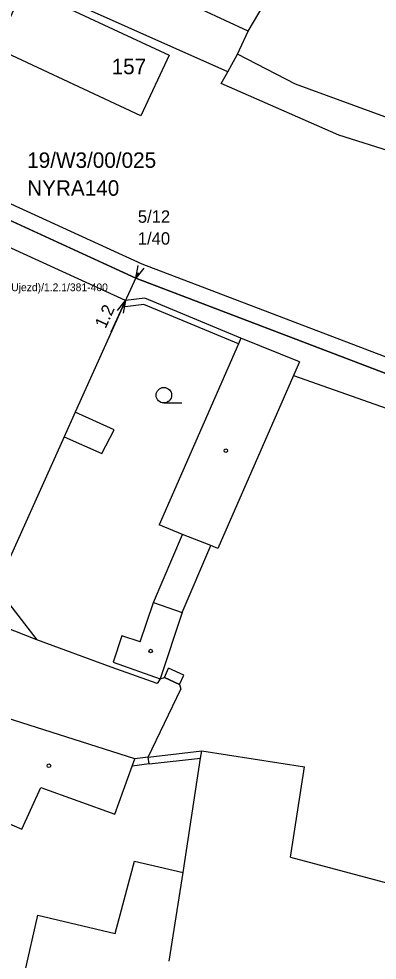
# Model space of a CAD drawing. Extents: x -836739 to -834468, y -1071001 to -1070126.
# Drawn here: x -836621.68 to -836604.33, y -1070455.07 to -1070409.44 of the extents above; entities that cross this region are included whole.
import ezdxf

# ---------------------------------------------------------------- set-up
doc = ezdxf.new("R2010")
doc.units = 0
for name, color, linetype in [('f001_pol_linie', 7, 'Continuous'), ('f001_pol_texty', 7, 'Continuous'), ('f001_pol_znacky', 7, 'Continuous'), ('f002_inz_linie_mimo_CETIN', 7, 'Continuous'), ('f004_popis_kab_zil', 7, 'Continuous'), ('f004_rozvadec_ann', 7, 'Continuous'), ('f006_osa_trasy', 7, 'Continuous'), ('f006_stp_koty', 7, 'Continuous'), ('f307_kabel_metal', 7, 'Continuous'), ('f307_rozvadec_ann', 7, 'Continuous')]:
    doc.layers.add(name, color=color, linetype=linetype)

msp = doc.modelspace()

# ---------------------------------------------------------------- linework, layer by layer
at = {"layer": 'f001_pol_linie'}
for points in [[(-836610.58, -1070410.04), (-836620.6, -1070405.38), (-836618.49, -1070400.85), (-836616.92, -1070397.47), (-836614.77, -1070392.87), (-836613.72, -1070393.26), (-836604.39, -1070397.96)], [(-836608.28, -1070412.62), (-836611.1, -1070411.16), (-836610.58, -1070410.04), (-836607.95, -1070405.59), (-836604.39, -1070397.96)], [(-836621.42, -1070407.93), (-836614.41, -1070411.21), (-836615.78, -1070414.14), (-836622.8, -1070410.87), (-836621.81, -1070408.77), (-836621.42, -1070407.93)], [(-836611.56, -1070412.01), (-836621.36, -1070407.64), (-836621.42, -1070407.93)], [(-836574.93, -1070422.97), (-836582.62, -1070420.71), (-836583.02, -1070422.31), (-836592.27, -1070419.48), (-836606.18, -1070415.08), (-836611.88, -1070412.58), (-836611.56, -1070412.01), (-836611.1, -1070411.16)], [(-836601.79, -1070414.98), (-836608.28, -1070412.62)], [(-836616.52, -1070423.1), (-836626.24, -1070418.65), (-836626.63, -1070418.47)], [(-836610.93, -1070424.93), (-836615.59, -1070422.99), (-836616.52, -1070423.1)], [(-836616.52, -1070423.1), (-836616.66, -1070423.42), (-836618.95, -1070428.51), (-836619.49, -1070429.7), (-836622.78, -1070437.01)], [(-836611.05, -1070425.2), (-836615.63, -1070423.3), (-836616.66, -1070423.42)], [(-836610.93, -1070424.93), (-836611.05, -1070425.2), (-836614.89, -1070433.98)], [(-836608.09, -1070426.07), (-836610.93, -1070424.93)], [(-836608.09, -1070426.07), (-836608.38, -1070426.73), (-836612.05, -1070435.12)], [(-836608.38, -1070426.73), (-836589.24, -1070433.48)], [(-836619.49, -1070429.7), (-836617.66, -1070430.52), (-836617.06, -1070429.36), (-836618.95, -1070428.51)], [(-836620.81, -1070439.55), (-836631.03, -1070435.52), (-836635.98, -1070433.29), (-836638.41, -1070431.73), (-836639.64, -1070430.3), (-836639.98, -1070429.29)], [(-836612.05, -1070435.12), (-836612.39, -1070434.98), (-836613.76, -1070434.44), (-836614.89, -1070433.98)], [(-836615.17, -1070437.74), (-836613.76, -1070434.44)], [(-836613.78, -1070438.23), (-836612.39, -1070434.98)], [(-836622.78, -1070437.01), (-836620.81, -1070439.55)], [(-836615.81, -1070439.65), (-836615.17, -1070437.74)], [(-836615.17, -1070437.74), (-836613.78, -1070438.23)], [(-836613.78, -1070438.23), (-836614.84, -1070441.43)], [(-836616.7, -1070439.35), (-836617.12, -1070440.63)], [(-836615.81, -1070439.65), (-836616.7, -1070439.35)], [(-836614.84, -1070441.43), (-836614.99, -1070441.66), (-836617.21, -1070440.88), (-836620.81, -1070439.55)], [(-836617.12, -1070440.63), (-836614.84, -1070441.43)], [(-836614.84, -1070441.43), (-836614.63, -1070441.38), (-836613.9, -1070441.72)], [(-836613.9, -1070441.72), (-836613.84, -1070441.94)], [(-836615.42, -1070445.23), (-836613.84, -1070441.94)], [(-836616.07, -1070445.32), (-836622.29, -1070443.32)], [(-836617.04, -1070448), (-836616.2, -1070445.67), (-836616.07, -1070445.32)], [(-836615.42, -1070445.23), (-836616.07, -1070445.32)], [(-836615.42, -1070445.23), (-836612.82, -1070444.93)], [(-836615.37, -1070445.56), (-836615.42, -1070445.23)], [(-836615.37, -1070445.56), (-836612.88, -1070445.29)], [(-836614.4, -1070455.13), (-836613.73, -1070450.82), (-836612.88, -1070445.29), (-836612.82, -1070444.93)], [(-836612.82, -1070444.93), (-836607.85, -1070445.7)], [(-836615.37, -1070445.56), (-836616.2, -1070445.67)], [(-836608.53, -1070450.08), (-836607.85, -1070445.7)], [(-836621.54, -1070448.73), (-836620.62, -1070446.7)], [(-836620.62, -1070446.7), (-836617.04, -1070448)], [(-836624.21, -1070447.58), (-836621.54, -1070448.73)], [(-836616.17, -1070459.86), (-836616.95, -1070459.66), (-836622.02, -1070458.45), (-836620.76, -1070452.9), (-836617.02, -1070453.79), (-836616.09, -1070450.28), (-836613.73, -1070450.82)], [(-836608.53, -1070450.08), (-836592.12, -1070454.46)]]:
    msp.add_lwpolyline(points, dxfattribs=at)
at = {"layer": 'f001_pol_znacky'}
msp.add_line((-836614.66, -1070428.065), (-836613.785, -1070428.065), dxfattribs=at)
for centre, radius in [((-836614.66, -1070427.69), 0.375), ((-836611.66, -1070430.38), 0.0875), ((-836615.3, -1070440.09), 0.0875), ((-836620.23, -1070445.65), 0.0875)]:
    msp.add_circle(centre, radius, dxfattribs=at)
at = {"layer": 'f002_inz_linie_mimo_CETIN'}
for points in [[(-836614.63, -1070441.38), (-836614.44, -1070440.92)], [(-836613.69, -1070441.26), (-836614.44, -1070440.92)], [(-836613.9, -1070441.72), (-836613.69, -1070441.26)], [(-836613.9, -1070441.72), (-836614.63, -1070441.38)]]:
    msp.add_lwpolyline(points, dxfattribs=at)
at = {"layer": 'f006_osa_trasy'}
msp.add_lwpolyline([(-836591.12, -1070431.51), (-836616.02, -1070422.01), (-836626.13, -1070417.38), (-836633.15, -1070414.46)], dxfattribs=at)
at = {"layer": 'f006_stp_koty'}
for points in [[(-836615.633, -1070421.524), (-836616.02, -1070422.008), (-836615.906, -1070421.4)], [(-836617.216, -1070424.62), (-836615.895, -1070421.736)], [(-836616.906, -1070423.583), (-836616.52, -1070423.1), (-836616.633, -1070423.707)]]:
    msp.add_lwpolyline(points, dxfattribs=at)
at = {"layer": 'f307_kabel_metal'}
for points in [[(-836629.321, -1070419.428), (-836629.463, -1070417.757), (-836629.739, -1070417.647), (-836632.42, -1070416.579), (-836631.832, -1070415.192), (-836631.383, -1070414.555), (-836631.289, -1070414.422), (-836625.83, -1070416.693), (-836624.501, -1070417.301), (-836623.819, -1070417.614), (-836615.73, -1070421.318), (-836590.874, -1070430.801), (-836587.05, -1070419.7)], [(-836629.321, -1070419.428), (-836629.185, -1070417.06), (-836629.461, -1070416.95), (-836631.43, -1070416.166), (-836631.173, -1070415.559), (-836631.022, -1070415.345), (-836630.96, -1070415.371), (-836630.268, -1070415.659), (-836626.13, -1070417.38), (-836624.131, -1070418.296), (-836623.449, -1070418.608), (-836616.02, -1070422.01), (-836591.12, -1070431.51), (-836590.415, -1070431.766), (-836578.78, -1070435.99)]]:
    msp.add_lwpolyline(points, dxfattribs=at)

# ---------------------------------------------------------------- texts
at = {"layer": 'f001_pol_texty'}
msp.add_text('157', height=0.75, dxfattribs=at).set_placement((-836617.19, -1070412.13))
at = {"layer": 'f004_popis_kab_zil'}
for s, p in [('5/12', (-836615.92, -1070419.33)), ('1/40', (-836615.92, -1070420.39))]:
    msp.add_text(s, height=0.6, dxfattribs=at).set_placement(p)
at = {"layer": 'f004_rozvadec_ann'}
for s, p in [('19/W3/00/025', (-836621.28, -1070416.67)), ('NYRA140', (-836621.28, -1070418.02))]:
    msp.add_text(s, height=0.75, dxfattribs=at).set_placement(p)
at = {"layer": 'f006_stp_koty'}
msp.add_text('1.2', height=0.6, rotation=65.39, dxfattribs=at).set_placement((-836617.487, -1070424.495))
at = {"layer": 'f307_rozvadec_ann'}
msp.add_text('19-W3-01NYRA22HR(K Ujezd)/1.2.1/381-400', height=0.375, dxfattribs=at).set_placement((-836627.573, -1070422.647))

doc.saveas('drawing.dxf')
